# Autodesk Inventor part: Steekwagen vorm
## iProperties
Created: 2007-06
Part Number: Steekwagen vorm
Document SubType Name: Modeling
Designer: Phil Trethewie
Author: Phil Trethewie
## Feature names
1. Extrusion1
2. Extrusion2
3. Extrusion3
